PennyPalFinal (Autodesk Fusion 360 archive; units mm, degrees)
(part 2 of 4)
extrude "Extrude119" add sketch "typec" profile of L10 L11 L12 L13 A11 L18 A10 A12 L19 L16 L17 A9 against normal blind 1.07
fillet "Fillet28" radius 1
fillet "Fillet29" radius 1
extrude "Extrude120" add of existing geometry to an object
extrude "Extrude121" cut sketch "typec" profile of A1 L1 A2 L2 A3 L3 A4 L4 A11 L18 A10 A12 L19 L16 L17 A9 against normal blind 8.1 bodies "previous"
sketch "boostersketch" plane through (0, 0, -56.6398) normal (0, 0, 1) x axis (-1, 0, 0)
  line L1 (32.6862, 10.13) -> (32.6862, -10.13)
  line L2 (7.5862, 10.13) -> (32.6862, 10.13)
  line L3 (7.5862, -10.13) -> (7.5862, 10.13)
  line L4 (32.6862, -10.13) -> (7.5862, -10.13)
  line L5 (34.6862, -8.13) -> (30.6862, -8.13)
  line L6 (34.6862, -12.13) -> (34.6862, -8.13)
  line L7 (30.6862, -12.13) -> (34.6862, -12.13)
  line L8 (30.6862, -8.13) -> (30.6862, -12.13)
  line L9 (34.6862, -12.13) -> (30.6862, -8.13)
  line L10 (30.6862, -12.13) -> (34.6862, -8.13)
  line L11 (9.5862, -12.13) -> (5.5862, -12.13)
  line L12 (9.5862, -8.13) -> (9.5862, -12.13)
  line L13 (5.5862, -8.13) -> (9.5862, -8.13)
  line L14 (5.5862, -12.13) -> (5.5862, -8.13)
  line L15 (9.5862, -8.13) -> (5.5862, -12.13)
  line L16 (5.5862, -8.13) -> (9.5862, -12.13)
  line L17 (34.6862, 8.13) -> (30.6862, 8.13)
  line L18 (34.6862, 12.13) -> (34.6862, 8.13)
  line L19 (30.6862, 12.13) -> (34.6862, 12.13)
  line L20 (30.6862, 8.13) -> (30.6862, 12.13)
  line L21 (34.6862, 12.13) -> (30.6862, 8.13)
  line L22 (30.6862, 12.13) -> (34.6862, 8.13)
  line L23 (9.5862, 8.13) -> (5.5862, 8.13)
  line L24 (9.5862, 12.13) -> (9.5862, 8.13)
  line L25 (5.5862, 12.13) -> (9.5862, 12.13)
  line L26 (5.5862, 8.13) -> (5.5862, 12.13)
  line L27 (9.5862, 12.13) -> (5.5862, 8.13)
  line L28 (5.5862, 12.13) -> (9.5862, 8.13)
  point P10 (32.6862, -10.13)
  point P2 (32.6862, -10.13)
  point P15 (7.5862, -10.13)
  point P5 (7.5862, -10.13)
  point P20 (32.6862, 10.13)
  point P3 (32.6862, 10.13)
  point P25 (7.5862, 10.13)
  point P4 (7.5862, 10.13)
  point P8 (34.6862, -12.13)
  point P9 (30.6862, -12.13)
  point P7 (34.6862, -8.13)
  point P13 (9.5862, -8.13)
  point P14 (5.5862, -8.13)
  point P12 (9.5862, -12.13)
  point P18 (34.6862, 12.13)
  point P19 (30.6862, 12.13)
  point P17 (34.6862, 8.13)
  point P23 (9.5862, 12.13)
  point P24 (5.5862, 12.13)
  point P22 (9.5862, 8.13)
  horizontal L5
  perpendicular L5 L6
  parallel L5 L7
  parallel L6 L8
  coincident L9 P10
  coincident L10 P10
  coincident P2 P10
  horizontal L11
  perpendicular L11 L12
  parallel L11 L13
  parallel L12 L14
  coincident L15 P15
  coincident L16 P15
  coincident P5 P15
  horizontal L17
  perpendicular L17 L18
  parallel L17 L19
  parallel L18 L20
  coincident L21 P20
  coincident L22 P20
  coincident P3 P20
  horizontal L23
  perpendicular L23 L24
  parallel L23 L25
  parallel L24 L26
  coincident L27 P25
  coincident L28 P25
  coincident P4 P25
  dimension "d476" distance P8 P9 = 4
  dimension "d477" distance P7 P8 = 4
  dimension "d478" distance P13 P14 = 4
  dimension "d479" distance P12 P13 = 4
  dimension "d480" distance P18 P19 = 4
  dimension "d481" distance P17 P18 = 4
  dimension "d482" distance P23 P24 = 4
  dimension "d483" distance P22 P23 = 4
extrude "Extrude122" add sketch "boostersketch" profile of L1 L2 L3 L4 L5 L6 L7 L8 L11 L12 L13 L14 L17 L18 L19 L20 L23 L24 L25 L26 to an object
extrude "Extrude123" add sketch "boostersketch" profile of L1 L2 L4 L5 L6 L7 L8 L17 L18 L19 L20 to an object
extrude "Extrude124" cut sketch "boostersketch" profile of L1 L2 L3 L4 L5 L8 L12 L13 L17 L20 L23 L24 against normal blind 1.7
offset_faces "OffsetFaces4" distance -0.1
offset_faces "OffsetFaces5" distance -0.2
extrude "Extrude125" cut sketch "typec" profile of A1 L1 A2 L2 A3 L3 A4 L4 L5 A5 L6 A6 L7 A7 L8 A8 A11 L18 A10 A12 L19 L16 L17 A9 against normal blind 3
sketch "Sketch29" plane through (0, 0, -40) normal (0, 0, 1) x axis (-1, 0, 0)
  line L1 (-36.619, -31.833) -> (-36.619, 2.775)
  line L2 (34.152, -33.833) -> (-34.619, -33.833)
  line L3 (36.152, 2.775) -> (36.152, -31.833)
  line L4 (-34.619, 4.775) -> (34.152, 4.775)
  arc A1 centre (-34.619, 2.775) radius 2 clockwise from (-36.619, 2.775) to (-34.619, 4.775)
  arc A2 centre (-34.619, -31.833) radius 2 clockwise from (-34.619, -33.833) to (-36.619, -31.833)
  arc A3 centre (34.152, -31.833) radius 2 clockwise from (36.152, -31.833) to (34.152, -33.833)
  arc A4 centre (34.152, 2.775) radius 2 clockwise from (34.152, 4.775) to (36.152, 2.775)
  circle C1 centre (31.199, -29.007) radius 1.6
  circle C2 centre (31.685, -18.165) radius 0.5461
  circle C3 centre (29.145, -18.165) radius 0.5461
  circle C4 centre (31.685, -15.625) radius 0.5461
  circle C5 centre (29.145, -15.625) radius 0.5461
  circle C6 centre (15.235, -16) radius 0.4
  circle C7 centre (0, -16) radius 0.4
  circle C8 centre (-9.314, -16.78) radius 0.7
  circle C9 centre (-9.314, -14.24) radius 0.7
  circle C10 centre (-24.564, -16.805) radius 0.7
  circle C11 centre (-24.564, -14.265) radius 0.7
  circle C12 centre (-32.174, -14.148) radius 0.5
  circle C13 centre (31.685, -13.085) radius 0.5461
  circle C14 centre (29.145, -13.085) radius 0.5461
  circle C15 centre (31.685, -10.545) radius 0.5461
  circle C16 centre (29.145, -10.545) radius 0.5461
  circle C17 centre (31.685, -8.005) radius 0.5461
  circle C18 centre (29.145, -8.005) radius 0.5461
  circle C19 centre (15.235, -13.46) radius 0.4
  circle C20 centre (15.235, -10.92) radius 0.4
  circle C21 centre (0, -13.46) radius 0.4
  circle C22 centre (0, -10.92) radius 0.4
  circle C23 centre (15.235, -8.38) radius 0.4
  circle C24 centre (15.235, -5.84) radius 0.4
  circle C25 centre (0, -8.38) radius 0.4
  circle C26 centre (0, -5.84) radius 0.4
  circle C27 centre (31.335, -2.83) radius 0.5
  circle C28 centre (31.335, -0.29) radius 0.5
  circle C29 centre (31.335, 2.25) radius 0.5
  circle C30 centre (15.235, -3.3) radius 0.4
  circle C31 centre (0, -3.3) radius 0.4
  circle C32 centre (15.235, -0.76) radius 0.4
  circle C33 centre (0, -0.76) radius 0.4
  circle C34 centre (-9.314, -11.7) radius 0.7
  circle C35 centre (-9.314, -9.16) radius 0.7
  circle C36 centre (-9.314, -6.62) radius 0.7
  circle C37 centre (-24.564, -11.725) radius 0.7
  circle C38 centre (-32.174, -11.608) radius 0.5
  circle C39 centre (-24.564, -9.185) radius 0.7
  circle C40 centre (-24.564, -6.645) radius 0.7
  circle C41 centre (-9.314, -4.08) radius 0.7
  circle C42 centre (-9.314, -1.54) radius 0.7
  circle C43 centre (-9.314, 1) radius 0.7
  circle C44 centre (-24.564, -4.105) radius 0.7
  circle C45 centre (-24.564, -1.565) radius 0.7
  circle C46 centre (-24.564, 0.975) radius 0.7
  circle C47 centre (-31.285, -0.686) radius 1.6
  circle C48 centre (-31.285, -0.686) radius 3
  circle C49 centre (31.199, -29.007) radius 3
  concentric C47 C48
  concentric C1 C49
  dimension "d494" diameter C48 = 6
  dimension "d495" diameter C49 = 6
extrude "Extrude126" add sketch "Sketch29" profile of C47 C48 to an object bodies "chamber"
extrude "Extrude127" add sketch "Sketch29" profile of C1 C49 to an object
sketch "coinplateboss" plane through (0, 0, 34.7705) normal (0, 0, 1) x axis (-1, 0, 0)
  line L1 (17.5, 9) -> (-17.5, 9)
  line L2 (17.5, 55) -> (17.5, 9)
  line L3 (-17.5, 55) -> (17.5, 55)
  line L4 (-17.5, 9) -> (-17.5, 55)
  line L5 (17.486, 0) -> (-20, 0)
  line L6 (0, 22) -> (0, 42)
  circle C1 centre (13.1388, 44.2682) radius 0.9
  circle C2 centre (13.1388, 44.2682) radius 3
  circle C3 centre (-13.1388, 44.2682) radius 0.9
  circle C4 centre (-13.1388, 44.2682) radius 3
  circle C5 centre (13.1388, -44.2682) radius 0.9
  circle C6 centre (13.1388, -44.2682) radius 3
  circle C7 centre (-13.1388, -44.2682) radius 0.9
  circle C8 centre (-13.1388, -44.2682) radius 3
  horizontal L5
  concentric C1 C2
  vertical L6
  symmetric C1 L6 C3
  symmetric C2 L6 C4
  symmetric L5 C1 C5
  symmetric L5 C2 C6
  symmetric L5 C3 C7
  symmetric L5 C4 C8
  dimension "d501" diameter C1 = 1.8
  dimension "d502" diameter C2 = 6
extrude "Extrude128" cut sketch "coinplateboss" profile of C1 C3 C5 C7 against normal blind 10
extrude "Extrude129" add sketch "coinplateboss" profile of C1 C2 C3 C4 to an object
extrude "Extrude130" add sketch "coinplateboss" profile of C5 C6 C7 C8 to an object
sketch "Sketch32" plane through (0, 0, 0) normal (0, 1, 0) x axis (1, 0, 0)
  line L1 (19.9, -26) -> (-17.5, -26)
  line L2 (-17.5, 32.7705) -> (17.5, 32.7705)
  line L3 (24.316, -26) -> (24.316, -32.0538)
  line L4 (19.9, -26) -> (24.316, -26)
  line L5 (-21.76, -26) -> (-21.76, -32.4924)
  line L6 (-17.5, -26) -> (-21.76, -26)
  line L7 (-21.76, -26) -> (-21.76, -32.4924)
  line L8 (-17.5, -26) -> (-21.76, -26)
  line L9 (19.9, -26) -> (-17.5, -26)
  line L10 (19.9, -26) -> (24.316, -26)
  line L11 (24.316, -26) -> (24.316, -32.0538)
  line L12 (-17.5, -32.8326) -> (17.5, -32.8326)
  line L13 (50.2705, 0) -> (0, 0)
  line L14 (-50.2705, 0) -> (0, 0)
  line L15 (50.2362, 1.5) -> (49.2705, 1.5)
  line L16 (51.7705, -1.5) -> (51.7705, 1.5)
  line L17 (49.2705, -1.5) -> (50.2362, -1.5)
  line L18 (48.7705, 1) -> (48.7705, -1)
  line L19 (51.7705, -1.5) -> (48.7705, 1.5)
  line L20 (48.7705, -1.5) -> (51.7705, 1.5)
  line L21 (0, -13) -> (0, 0)
  line L22 (-50.2362, 1.5) -> (-49.2705, 1.5)
  line L23 (-49.2705, -1.5) -> (-50.2362, -1.5)
  line L24 (-48.7705, 1) -> (-48.7705, -1)
  line L25 (-17.5, 32.7705) -> (17.5, 32.7705)
  line L26 (-17.5, 30.7705) -> (17.5, 30.7705)
  line L27 (46.7705, 1) -> (46.7705, -1)
  line L28 (-46.7705, 1) -> (-46.7705, -1)
  line L29 (49.2705, -1.8) -> (50.221, -1.8)
  line L30 (48.4705, 1) -> (48.4705, -1)
  line L31 (50.221, 1.8) -> (49.2705, 1.8)
  line L32 (-49.2705, -1.8) -> (-50.221, -1.8)
  line L33 (-48.4705, 1) -> (-48.4705, -1)
  line L34 (-50.221, 1.8) -> (-49.2705, 1.8)
  arc A1 centre (-17.5, 0) radius 32.7705 clockwise from (-17.5, -32.7705) to (-36, -27.0491)
  arc A2 centre (17.5, 0) radius 32.7705 clockwise from (36, -27.0491) to (17.5, -32.7705)
  arc A3 centre (-17.5, 0) radius 32.7705 clockwise from (-36, -27.0491) to (-17.5, 32.7705)
  arc A4 centre (17.5, 0) radius 32.7705 clockwise from (17.5, 32.7705) to (36, -27.0491)
  arc A5 centre (49.2705, -1) radius 0.5 clockwise from (49.2705, -1.5) to (48.7705, -1)
  arc A6 centre (49.2705, 1) radius 0.5 clockwise from (48.7705, 1) to (49.2705, 1.5)
  arc A7 centre (-49.2705, -1) radius 0.5 clockwise from (-48.7705, -1) to (-49.2705, -1.5)
  arc A8 centre (-49.2705, 1) radius 0.5 clockwise from (-49.2705, 1.5) to (-48.7705, 1)
  arc A9 centre (17.5, 0) radius 30.7705 clockwise from (34.8709, -25.3983) to (24.316, -30.0061)
  arc A10 centre (-17.5, 0) radius 30.7705 clockwise from (-21.76, -30.4742) to (-34.8709, -25.3983)
  arc A11 centre (49.2705, -1) radius 2.5 clockwise from (48.1026, -3.2104) to (46.7705, -1)
  arc A12 centre (49.2705, 1) radius 2.5 clockwise from (46.7705, 1) to (48.1026, 3.2104)
  arc A13 centre (17.5, 0) radius 30.7705 clockwise from (48.1026, -3.2104) to (34.8709, -25.3983)
  arc A14 centre (17.5, 0) radius 30.7705 clockwise from (17.5, 30.7705) to (48.1026, 3.2104)
  arc A15 centre (-49.2705, -1) radius 2.5 clockwise from (-46.7705, -1) to (-48.1026, -3.2104)
  arc A16 centre (-49.2705, 1) radius 2.5 clockwise from (-48.1026, 3.2104) to (-46.7705, 1)
  arc A17 centre (-17.5, 0) radius 30.7705 clockwise from (-48.1026, 3.2104) to (-17.5, 30.7705)
  arc A18 centre (-17.5, 0) radius 30.7705 clockwise from (-34.8709, -25.3983) to (-48.1026, -3.2104)
  arc A19 centre (49.2705, -1) radius 0.8 clockwise from (49.2705, -1.8) to (48.4705, -1)
  arc A20 centre (49.2705, 1) radius 0.8 clockwise from (48.4705, 1) to (49.2705, 1.8)
  arc A21 centre (-49.2705, -1) radius 0.8 clockwise from (-48.4705, -1) to (-49.2705, -1.8)
  arc A22 centre (-49.2705, 1) radius 0.8 clockwise from (-49.2705, 1.8) to (-48.4705, 1)
  point P3 (19.9, -26)
  point P18 (19.9, -26)
  point P2 (-17.5, -26)
  point P21 (-17.5, -26)
  point P1 (0, 0)
  point P30 (0, 0)
  point P31 (50.2705, 0)
  point P32 (-50.2705, 0)
  point P37 (50.2705, 0)
  point P38 (-50.2705, 0)
  point P39 (50.2362, -1.5)
  point P40 (50.2362, 1.5)
  point P36 (48.7705, -1.5)
  point P33 (48.7705, 1.5)
  point P55 (-50.2362, -1.5)
  point P54 (-50.2362, 1.5)
  point P41 (49.2705, -1.5)
  point P50 (-49.2705, -1.5)
  point P42 (48.7705, -1)
  point P49 (-48.7705, -1)
  point P44 (49.2705, 1.5)
  point P52 (-49.2705, 1.5)
  point P45 (48.7705, 1)
  point P53 (-48.7705, 1)
  point P70 (24.316, -30.0061)
  point P71 (-21.76, -30.4742)
  point P73 (46.7705, -1)
  point P80 (-46.7705, -1)
  point P74 (46.7705, 1)
  point P82 (-46.7705, 1)
  point P76 (48.1026, -3.2104)
  point P81 (-48.1026, -3.2104)
  point P78 (48.1026, 3.2104)
  point P84 (-48.1026, 3.2104)
  point P92 (50.221, -1.8)
  point P93 (50.221, 1.8)
  point P86 (49.2705, -1.8)
  point P95 (-49.2705, -1.8)
  point P88 (48.4705, -1)
  point P97 (-48.4705, -1)
  point P89 (48.4705, 1)
  point P98 (-48.4705, 1)
  point P91 (49.2705, 1.8)
  point P100 (-49.2705, 1.8)
  point P94 (-50.221, -1.8)
  point P101 (-50.221, 1.8)
  point P35 (51.7705, -1.5)
  point P34 (51.7705, 1.5)
  perpendicular L1 L3
  coincident P3 P18
  perpendicular L1 L5
  coincident P2 P21
  coincident P1 P30
  coincident A4 P31
  horizontal L13
  coincident A3 P32
  parallel L13 L14
  horizontal L15
  perpendicular L15 L16
  parallel L15 L17
  parallel L16 L18
  coincident L19 P37
  coincident L20 P37
  coincident P31 P37
  coincident P32 P38
  coincident A4 P39
  coincident A4 P40
  coincident P36 L17
  coincident P36 L18
  tangent L17 A5
  tangent L18 A5
  coincident P33 L15
  coincident P33 L18
  tangent L15 A6
  tangent L18 A6
  equal A5 A6
  perpendicular L14 L21
  symmetric P39 L21 P55
  symmetric P40 L21 P54
  symmetric P41 L21 P50
  symmetric P42 L21 P49
  symmetric A5 L21 A7
  symmetric P44 L21 P52
  symmetric P45 L21 P53
  symmetric A6 L21 A8
  concentric A2 A9
  coincident L3 P70
  concentric A1 A10
  coincident L5 P71
  concentric A5 A11
  concentric A6 A12
  tangent L27 A12
  tangent A11 L27
  concentric A4 A13
  concentric A13 A14
  symmetric L21 P73 P80
  symmetric L21 A11 A15
  symmetric L21 P74 P82
  symmetric L21 A12 A16
  symmetric L21 P76 P81
  symmetric L21 P78 P84
  concentric A3 A17
  concentric A17 A18
  concentric A5 A19
  concentric A6 A20
  tangent A19 L30
  tangent L30 A20
  tangent A20 L31
  tangent L29 A19
  coincident A4 P92
  coincident A4 P93
  symmetric L21 P86 P95
  symmetric L21 P88 P97
  symmetric L21 A19 A21
  symmetric L21 P89 P98
  symmetric L21 P91 P100
  symmetric L21 A20 A22
  symmetric L21 P92 P94
  symmetric L21 P93 P101
  dimension "d514" distance L3 = 0
  dimension "d515" distance P35 P36 = 3
  dimension "d516" distance P34 P35 = 3
  dimension "d521" radius A5 = 0.5
  dimension "d533" distance L2 = 0
  dimension "d534" = -2
extrude "Extrude133" add sketch "Sketch32" profile of A3 A4 L15 L17 L18 A5 A6 A7 A8 L22 L23 L24 along normal blind 55 and against normal blind 55
extrude "Extrude134" new body sketch "Sketch32" profile of A1 A2 L2 A3 A4 L3 L5 L11 L7 A14 A9 A10 A18 L25 L26 L27 A11 A12 A15 L28 A16 L30 L31 A19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 along normal blind 55 and against normal blind 55 bodies "drawer"
offset_faces "OffsetFaces6" distance -0.2
sketch "Sketch33" plane through (0, 55, 0) normal (0, 1, 0) x axis (-1, 0, 0)
  line L1 (21.76, 30.4742) -> (21.76, 32.2907)
  line L2 (-17.5, -30.7705) -> (17.5, -30.7705)
  line L3 (-24.316, 31.8493) -> (-24.316, 30.0061)
  line L4 (17.5, -32.5705) -> (-17.5, -32.5705)
  line L5 (-24.316, 30) -> (-24.316, 31.8493)
  line L6 (21.76, 30) -> (21.76, 32.2907)
  line L7 (-20.316, 26) -> (0, 26)
  line L8 (17.76, 26) -> (0, 26)
  line L9 (17.5, -34.7705) -> (-17.5, -34.7705)
  line L10 (17.5, -29.2705) -> (-17.5, -29.2705)
  line L11 (17.5, -32.5705) -> (-17.5, -32.5705)
  line L12 (17.5, -30.5705) -> (-17.5, -30.5705)
  line L13 (48.4705, 1) -> (48.4705, -1)
  line L14 (50.0207, 1.8) -> (49.2705, 1.8)
  line L15 (49.2705, -1.8) -> (50.0207, -1.8)
  line L16 (46.7705, -1) -> (46.7705, 1)
  line L17 (-49.2705, 1.8) -> (-50.0207, 1.8)
  line L18 (-48.4705, -1) -> (-48.4705, 1)
  line L19 (-50.0207, -1.8) -> (-49.2705, -1.8)
  line L20 (-46.7705, 1) -> (-46.7705, -1)
  line L21 (-46.7705, 1) -> (-46.7705, -1)
  line L22 (46.7705, -1) -> (46.7705, 1)
  line L23 (-43.7705, 1) -> (-43.7705, -1)
  line L24 (43.7705, -1) -> (43.7705, 1)
  line L25 (-17.5, 34.7705) -> (17.5, 34.7705)
  line L26 (-17.5, 32.5705) -> (17.5, 32.5705)
  line L27 (-2, 32.5705) -> (-2, 26)
  line L28 (-20.316, 28) -> (0, 28)
  line L29 (17.76, 28) -> (0, 28)
  line L30 (-20.316, 31) -> (0, 31)
  line L31 (17.76, 31) -> (0, 31)
  line L32 (-20.316, 31) -> (-20.316, 28)
  line L33 (17.76, 31) -> (17.76, 28)
  line L34 (-20, 26) -> (-20.316, 28)
  line L35 (17.76, 26) -> (17.76, 28)
  arc A1 centre (17.5, 0) radius 32.5705 clockwise from (21.76, 32.2907) to (50.0207, 1.8)
  arc A2 centre (-17.5, 0) radius 32.5705 clockwise from (-50.0207, 1.8) to (-24.316, 31.8493)
  arc A3 centre (-17.5, 0) radius 32.5705 clockwise from (-17.5, -32.5705) to (-50.0207, -1.8)
  arc A4 centre (17.5, 0) radius 32.5705 clockwise from (50.0207, -1.8) to (17.5, -32.5705)
  arc A5 centre (17.5, 0) radius 29.5705 clockwise from (47.0705, 0) to (47.0705, -0.0001)
  arc A6 centre (17.5, 0) radius 34.7705 clockwise from (36, 29.4404) to (17.5, -34.7705)
  arc A7 centre (-17.5, 0) radius 34.7705 clockwise from (-17.5, -34.7705) to (-36, 29.4404)
  arc A8 centre (-17.5, 0) radius 34.7705 clockwise from (-36, 29.4404) to (-17.5, 34.7705)
  arc A9 centre (17.5, 0) radius 34.7705 clockwise from (17.5, 34.7705) to (36, 29.4404)
  arc A10 centre (-17.5, 0) radius 29.2705 clockwise from (-33.0737, 24.7835) to (-24.316, 28.4659)
  arc A11 centre (17.5, 0) radius 29.2705 clockwise from (21.76, 28.9589) to (33.0737, 24.7835)
  arc A12 centre (17.5, 0) radius 32.5705 clockwise from (21.76, 32.2907) to (34.8295, 27.5777)
  arc A13 centre (-17.5, 0) radius 32.5705 clockwise from (-34.8295, 27.5777) to (-24.316, 31.8493)
  arc A14 centre (17.5, 0) radius 30.5705 clockwise from (21.76, 30.2722) to (33.7653, 25.8843)
  arc A15 centre (-17.5, 0) radius 30.5705 clockwise from (-33.7653, 25.8843) to (-24.316, 29.801)
  arc A16 centre (49.2705, 1) radius 0.8 clockwise from (48.4705, 1) to (49.2705, 1.8)
  arc A17 centre (49.2705, -1) radius 0.8 clockwise from (49.2705, -1.8) to (48.4705, -1)
  arc A18 centre (49.2705, -1) radius 2.5 clockwise from (48.1026, -3.2104) to (46.7705, -1)
  arc A19 centre (49.2705, 1) radius 2.5 clockwise from (46.7705, 1) to (48.1026, 3.2104)
  arc A20 centre (-49.2705, 1) radius 0.8 clockwise from (-49.2705, 1.8) to (-48.4705, 1)
  arc A21 centre (-49.2705, -1) radius 0.8 clockwise from (-48.4705, -1) to (-49.2705, -1.8)
  arc A22 centre (-49.2705, 1) radius 2.5 clockwise from (-48.1026, 3.2104) to (-46.7705, 1)
  arc A23 centre (-49.2705, -1) radius 2.5 clockwise from (-46.7705, -1) to (-48.1026, -3.2104)
  arc A24 centre (-49.2705, -1) radius 2.5 clockwise from (-46.7705, -1) to (-49.8902, -3.422)
  arc A25 centre (-49.2705, 1) radius 2.5 clockwise from (-49.8902, 3.422) to (-46.7705, 1)
  arc A26 centre (-17.5, 0) radius 32.5705 clockwise from (-49.8902, 3.422) to (-34.8295, 27.5777)
  arc A27 centre (-17.5, 0) radius 32.5705 clockwise from (-17.5, -32.5705) to (-49.8902, -3.422)
  arc A28 centre (-17.5, 0) radius 29.2705 clockwise from (-46.2327, 5.585) to (-33.0737, 24.7835)
  arc A29 centre (-17.5, 0) radius 29.2705 clockwise from (-17.5, -29.2705) to (-46.2327, -5.585)
  arc A30 centre (-17.5, 0) radius 30.5705 clockwise from (-47.913, 3.0993) to (-33.7653, 25.8843)
  arc A31 centre (-17.5, 0) radius 30.5705 clockwise from (-17.5, -30.5705) to (-47.913, -3.0993)
  arc A32 centre (49.2705, 1) radius 2.5 clockwise from (46.7705, 1) to (49.8902, 3.422)
  arc A33 centre (49.2705, -1) radius 2.5 clockwise from (49.8902, -3.422) to (46.7705, -1)
  arc A34 centre (17.5, 0) radius 32.5705 clockwise from (34.8295, 27.5777) to (49.8902, 3.422)
  arc A35 centre (17.5, 0) radius 32.5705 clockwise from (49.8902, -3.422) to (17.5, -32.5705)
  arc A36 centre (17.5, 0) radius 29.2705 clockwise from (46.2327, -5.585) to (17.5, -29.2705)
  arc A37 centre (17.5, 0) radius 29.2705 clockwise from (33.0737, 24.7835) to (46.2327, 5.585)
  arc A38 centre (49.2705, 1) radius 4.5 clockwise from (49.6049, 5.4876) to (49.6643, 5.4827)
  arc A39 centre (17.5, 0) radius 30.5705 clockwise from (47.913, -3.0993) to (17.5, -30.5705)
  arc A40 centre (17.5, 0) radius 30.5705 clockwise from (33.7653, 25.8843) to (47.913, 3.0993)
  arc A41 centre (-49.2705, 1) radius 5.5 clockwise from (-46.2327, 5.585) to (-43.7705, 1)
  arc A42 centre (-49.2705, -1) radius 5.5 clockwise from (-43.7705, -1) to (-46.2327, -5.585)
  arc A43 centre (49.2705, 1) radius 5.5 clockwise from (43.7705, 1) to (46.2327, 5.585)
  arc A44 centre (49.2705, -1) radius 5.5 clockwise from (46.2327, -5.585) to (43.7705, -1)
  arc A45 centre (17.5, 0) radius 32.5705 clockwise from (17.5, 32.5705) to (34.8295, 27.5777)
  arc A46 centre (-17.5, 0) radius 32.5705 clockwise from (-34.8295, 27.5777) to (-17.5, 32.5705)
  arc A47 centre (17.5, 0) radius 30.5705 clockwise from (21.76, 30.2722) to (33.7653, 25.8843)
  arc A48 centre (-17.5, 0) radius 30.5705 clockwise from (-33.7653, 25.8843) to (-24.3111, 29.8021)
  arc A49 centre (17.5, 0) radius 29.2705 clockwise from (21.6272, 28.9781) to (33.0737, 24.7835)
  arc A50 centre (-17.5, 0) radius 29.2705 clockwise from (-33.0737, 24.7835) to (-24.0366, 28.5313)
  arc A51 centre (-20.316, 30) radius 4 clockwise from (-20.316, 26) to (-24.316, 30)
  arc A52 centre (17.76, 30) radius 4 clockwise from (21.76, 30) to (17.76, 26)
  point P10 (-24.316, 31.8493)
  point P19 (-24.316, 31.8493)
  point P3 (21.76, 32.2907)
  point P20 (21.76, 32.2907)
  point P44 (-24.316, 28.4659)
  point P45 (21.76, 28.9589)
  point P68 (-24.316, 29.801)
  point P69 (21.76, 30.2722)
  point P101 (-49.8902, -3.422)
  point P108 (-47.913, 3.0993)
  point P109 (-47.913, -3.0993)
  point P119 (49.6049, 5.4876)
  point P120 (47.913, -3.0993)
  point P121 (47.913, 3.0993)
  point P159 (-24.3111, 29.8021)
  point P160 (-24.0366, 28.5313)
  point P161 (21.6272, 28.9781)
  point P162 (-2, 26)
  point P163 (-2, 32.5705)
  point P172 (-20, 26)
  coincident P10 P19
  parallel L3 L5
  coincident P3 P20
  parallel L1 L6
  perpendicular L5 L7
  parallel L7 L8
  tangent L10 A36
  concentric A8 A10
  coincident L5 P44
  concentric A9 A11
  coincident L6 P45
  concentric A9 A12
  concentric A8 A13
  concentric A13 A15
  coincident L5 P68
  concentric A12 A14
  coincident L6 P69
  coincident A3 P101
  concentric A7 A26
  concentric A6 A35
  tangent L11 A27
  tangent L11 A35
  concentric A26 A30
  concentric A26 A27
  tangent A24 L21
  tangent L21 A25
  concentric A7 A28
  concentric A28 A29
  coincident A22 P108
  coincident A23 P109
  concentric A30 A31
  concentric A35 A39
  concentric A32 A38
  tangent L22 A33
  tangent A32 L22
  concentric A6 A36
  concentric A36 A37
  coincident A1 P119
  coincident A18 P120
  coincident A19 P121
  concentric A39 A40
  tangent L5 A51
  tangent L7 A51
  tangent L8 A52
  tangent L6 A52
  equal A51 A52
  concentric A45 A47
  concentric A46 A48
  concentric A47 A49
  concentric A48 A50
  coincident A51 P159
  coincident A51 P160
  coincident A52 P161
  coincident L7 P162
  coincident L26 P163
  perpendicular L26 L27
  perpendicular L30 L32
  perpendicular L31 L33
  coincident L7 P172
  perpendicular L8 L35
  dimension "d571" = -2
  dimension "d597" = -2.2
  dimension "d598" distance A15 A46 = 2
  dimension "d601" radius A51 = 4
  dimension "d691" = 2
  dimension "d692" = -2
  dimension "d693" = 3
  dimension "d694" = -3
extrude "Extrude136" new body sketch "Sketch33" profile of A1 L1 L2 L3 A2 A3 L4 A4 L5 L6 A37 A29 L10 A10 A11 A35 L11 A27 A12 A13 along normal blind 2
extrude "Extrude137" new body of existing geometry blind 2 bodies "drawerfront"
move "Move10"
extrude "Extrude138" new body sketch "Sketch33" profile of L5 L6 L7 L8 A37 A29 L10 A10 A11 along normal blind 1.8 bodies "acrylic"
move "Move11"
offset_faces "OffsetFaces7" distance 1
extrude "Extrude139" add sketch "Sketch33" profile of L1 L3 L5 L6 L7 L8 A37 A29 L10 A10 A11 A41 L23 A42 A43 L24 A44 A46 L26 A45 A50 A49 A51 A52 along normal blind 2 bodies "acrylic"
extrude "Extrude140" add sketch "Sketch33" profile of L3 A2 L5 L7 L8 A37 A29 L10 A10 A11 A27 A13 A31 A15 A22 A25 A41 L23 A42 A43 L24 A44 A46 A48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 along normal blind 2
move "Move12"
extrude "Extrude142" add sketch "Sketch33" profile of A3 L4 A4 A35 L11 A27 A40 L12 A31 A18 A23 A24 A33 against normal blind 2
remove_body "RemoveBody29"
copy_paste_bodies "CopyPasteBodies2"
move "Move14"
extrude "Extrude143" add sketch "Sketch33" profile of A1 L1 L3 A2 A3 L4 A4 L5 L6 A35 L11 A27 A12 A13 A14 A40 L12 A31 A15 A18 A19 A22 A23 A25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 against normal blind 3.8
extrude "Extrude144" add of existing geometry blind 2
extrude "Extrude145" add sketch "Sketch33" profile of L1 L3 L5 L6 L7 L8 A46 L26 A45 A51 A52 to an object
sketch "accrylicsketch" plane through (0, 55, 0) normal (0, 1, 0) x axis (-1, 0, 0)
  line L1 (-46.7705, -1) -> (-46.7705, 1)
  line L2 (17.5, -32.5705) -> (-17.5, -32.5705)
  line L3 (46.7705, 1) -> (46.7705, -1)
  line L4 (-17.5, 32.5705) -> (17.5, 32.5705)
  line L5 (17.76, 26) -> (-20.316, 26)
  line L6 (43.7705, -1) -> (43.7705, 1)
  line L7 (-17.5, -29.2705) -> (17.5, -29.2705)
  line L8 (-43.7705, 1) -> (-43.7705, -1)
  line L9 (-44.7705, 1) -> (-44.7705, -1)
  line L10 (-17.5, -30.2705) -> (17.5, -30.2705)
  line L11 (44.7705, -1) -> (44.7705, 1)
  line L12 (-24.0366, 29.5563) -> (-24.0366, 28.5313)
  line L13 (21.6272, 29.9878) -> (21.6272, 28.9781)
  arc A1 centre (-17.5, 0) radius 32.5705 clockwise from (-49.8902, 3.422) to (-17.5, 32.5705)
  arc A2 centre (-49.2705, 1) radius 2.5 clockwise from (-49.8902, 3.422) to (-46.7705, 1)
  arc A3 centre (-49.2705, -1) radius 2.5 clockwise from (-46.7705, -1) to (-49.8902, -3.422)
  arc A4 centre (-17.5, 0) radius 32.5705 clockwise from (-17.5, -32.5705) to (-49.8902, -3.422)
  arc A5 centre (17.5, 0) radius 32.5705 clockwise from (49.8902, -3.422) to (17.5, -32.5705)
  arc A6 centre (49.2705, -1) radius 2.5 clockwise from (49.8902, -3.422) to (46.7705, -1)
  arc A7 centre (49.2705, 1) radius 2.5 clockwise from (46.7705, 1) to (49.8902, 3.422)
  arc A8 centre (17.5, 0) radius 32.5705 clockwise from (17.5, 32.5705) to (49.8902, 3.422)
  arc A9 centre (-20.316, 30) radius 4 clockwise from (-20.316, 26) to (-24.0366, 28.5313)
  arc A10 centre (17.76, 30) radius 4 clockwise from (21.6272, 28.9781) to (17.76, 26)
  arc A11 centre (17.5, 0) radius 29.2705 clockwise from (21.6272, 28.9781) to (46.2327, 5.585)
  arc A12 centre (49.2705, 1) radius 5.5 clockwise from (43.7705, 1) to (46.2327, 5.585)
  arc A13 centre (49.2705, -1) radius 5.5 clockwise from (46.2327, -5.585) to (43.7705, -1)
  arc A14 centre (17.5, 0) radius 29.2705 clockwise from (46.2327, -5.585) to (17.5, -29.2705)
  arc A15 centre (-17.5, 0) radius 29.2705 clockwise from (-17.5, -29.2705) to (-46.2327, -5.585)
  arc A16 centre (-49.2705, -1) radius 5.5 clockwise from (-43.7705, -1) to (-46.2327, -5.585)
  arc A17 centre (-49.2705, 1) radius 5.5 clockwise from (-46.2327, 5.585) to (-43.7705, 1)
  arc A18 centre (-17.5, 0) radius 29.2705 clockwise from (-46.2327, 5.585) to (-24.0366, 28.5313)
  arc A19 centre (17.5, 0) radius 30.2705 clockwise from (21.6272, 29.9878) to (47.3435, 5.0665)
  arc A20 centre (-17.5, 0) radius 30.2705 clockwise from (-47.3435, 5.0665) to (-24.0366, 29.5563)
  arc A21 centre (-49.2705, 1) radius 4.5 clockwise from (-47.3435, 5.0665) to (-44.7705, 1)
  arc A22 centre (-49.2705, -1) radius 4.5 clockwise from (-44.7705, -1) to (-47.3435, -5.0665)
  arc A23 centre (-17.5, 0) radius 30.2705 clockwise from (-17.5, -30.2705) to (-47.3435, -5.0665)
  arc A24 centre (17.5, 0) radius 30.2705 clockwise from (47.3435, -5.0665) to (17.5, -30.2705)
  arc A25 centre (49.2705, -1) radius 4.5 clockwise from (47.3435, -5.0665) to (44.7705, -1)
  arc A26 centre (49.2705, 1) radius 4.5 clockwise from (44.7705, 1) to (47.3435, 5.0665)
  point P20 (-24.0366, 28.5313)
  point P54 (-24.0366, 28.5313)
  point P24 (21.6272, 28.9781)
  point P56 (21.6272, 28.9781)
  coincident P20 P54
  vertical L12
  coincident P24 P56
  parallel L12 L13
  concentric A11 A19
  concentric A18 A20
  concentric A17 A21
  concentric A16 A22
  concentric A15 A23
  concentric A14 A24
  concentric A13 A25
  concentric A12 A26
  tangent L11 A26
  tangent A21 L9
  tangent A23 L10
  tangent L9 A22
  tangent L10 A24
  tangent A25 L11
extrude "Extrude146" new body sketch "accrylicsketch" profile of A9 L5 A10 A11 A12 L6 A13 A14 L7 A15 A16 L8 A17 A18 A26 L11 A25 A24 A19 L10 A22 L9 A20 A23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 against normal blind 3.8 bodies "acrylic"
extrude "Extrude147" cut of existing geometry blind -2
sketch "drawerpanel" plane through (0, -55, 0) normal (0, -1, 0) x axis (1, 0, 0)
  line L1 (36, 29.4404) -> (36, 27.0491)
  line L2 (-17.5, 34.7705) -> (17.5, 34.7705)
  line L3 (-36, 27.0491) -> (-36, 29.4404)
  line L4 (17.5, 32.7705) -> (-17.5, 32.7705)
  line L5 (43.7705, -1) -> (43.7705, 1)
  line L6 (-17.5, -29.2705) -> (17.5, -29.2705)
  line L7 (-43.7705, 1) -> (-43.7705, -1)
  line L8 (20.316, 26) -> (-17.76, 26)
  line L9 (-17.5, 32.5705) -> (17.5, 32.5705)
  line L10 (-46.7705, -1) -> (-46.7705, 1)
  line L11 (17.5, -32.5705) -> (-17.5, -32.5705)
  line L12 (46.7705, 1) -> (46.7705, -1)
  line L13 (24.0366, 28.5313) -> (24.0366, 29.5563)
  line L14 (-17.76, 26) -> (20.316, 26)
  line L15 (-21.6272, 29.9878) -> (-21.6272, 28.9781)
  line L16 (-44.7705, -1) -> (-44.7705, 1)
  line L17 (17.5, -30.2705) -> (-17.5, -30.2705)
  line L18 (44.7705, 1) -> (44.7705, -1)
  line L19 (-21.6272, 32.308) -> (-21.6272, 29.9878)
  line L20 (24.0366, 31.9079) -> (24.0366, 29.5563)
  line L21 (-21.6272, 32.5096) -> (-21.6272, 32.308)
  line L22 (24.0366, 32.2) -> (24.0366, 31.9079)
  arc A1 centre (17.5, 0) radius 34.7705 clockwise from (17.5, 34.7705) to (36, 29.4404)
  arc A2 centre (-17.5, 0) radius 34.7705 clockwise from (-36, 29.4404) to (-17.5, 34.7705)
  arc A3 centre (-17.5, 0) radius 32.7705 clockwise from (-36, 27.0491) to (-17.5, 32.7705)
  arc A4 centre (17.5, 0) radius 32.7705 clockwise from (17.5, 32.7705) to (36, 27.0491)
  arc A5 centre (17.5, 0) radius 29.2705 clockwise from (24.0366, 28.5313) to (46.2327, 5.585)
  arc A6 centre (49.2705, 1) radius 5.5 clockwise from (43.7705, 1) to (46.2327, 5.585)
  arc A7 centre (49.2705, -1) radius 5.5 clockwise from (46.2327, -5.585) to (43.7705, -1)
  arc A8 centre (17.5, 0) radius 29.2705 clockwise from (46.2327, -5.585) to (17.5, -29.2705)
  arc A9 centre (-17.5, 0) radius 29.2705 clockwise from (-17.5, -29.2705) to (-46.2327, -5.585)
  arc A10 centre (-49.2705, -1) radius 5.5 clockwise from (-43.7705, -1) to (-46.2327, -5.585)
  arc A11 centre (-49.2705, 1) radius 5.5 clockwise from (-46.2327, 5.585) to (-43.7705, 1)
  arc A12 centre (-17.5, 0) radius 29.2705 clockwise from (-46.2327, 5.585) to (-21.6272, 28.9781)
  arc A13 centre (-17.76, 30) radius 4 clockwise from (-17.76, 26) to (-21.6272, 28.9781)
  arc A14 centre (20.316, 30) radius 4 clockwise from (24.0366, 28.5313) to (20.316, 26)
  arc A15 centre (17.5, 0) radius 32.5705 clockwise from (17.5, 32.5705) to (49.8902, 3.422)
  arc A16 centre (-17.5, 0) radius 32.5705 clockwise from (-49.8902, 3.422) to (-17.5, 32.5705)
  arc A17 centre (-49.2705, 1) radius 2.5 clockwise from (-49.8902, 3.422) to (-46.7705, 1)
  arc A18 centre (-49.2705, -1) radius 2.5 clockwise from (-46.7705, -1) to (-49.8902, -3.422)
  arc A19 centre (-17.5, 0) radius 32.5705 clockwise from (-17.5, -32.5705) to (-49.8902, -3.422)
  arc A20 centre (17.5, 0) radius 32.5705 clockwise from (49.8902, -3.422) to (17.5, -32.5705)
  arc A21 centre (49.2705, -1) radius 2.5 clockwise from (49.8902, -3.422) to (46.7705, -1)
  arc A22 centre (49.2705, 1) radius 2.5 clockwise from (46.7705, 1) to (49.8902, 3.422)
  arc A23 centre (20.316, 30) radius 4 clockwise from (24.0366, 28.5313) to (20.316, 26)
  arc A24 centre (-17.76, 30) radius 4 clockwise from (-17.76, 26) to (-21.6272, 28.9781)
  arc A25 centre (-17.5, 0) radius 30.2705 clockwise from (-47.3435, 5.0665) to (-21.6272, 29.9878)
  arc A26 centre (-49.2705, 1) radius 4.5 clockwise from (-47.3435, 5.0665) to (-44.7705, 1)
  arc A27 centre (-49.2705, -1) radius 4.5 clockwise from (-44.7705, -1) to (-47.3435, -5.0665)
  arc A28 centre (-17.5, 0) radius 30.2705 clockwise from (-17.5, -30.2705) to (-47.3435, -5.0665)
  arc A29 centre (17.5, 0) radius 30.2705 clockwise from (47.3435, -5.0665) to (17.5, -30.2705)
  arc A30 centre (49.2705, -1) radius 4.5 clockwise from (47.3435, -5.0665) to (44.7705, -1)
  arc A31 centre (49.2705, 1) radius 4.5 clockwise from (44.7705, 1) to (47.3435, 5.0665)
  arc A32 centre (17.5, 0) radius 30.2705 clockwise from (24.0366, 29.5563) to (47.3435, 5.0665)
  point P53 (-21.6272, 29.9878)
  point P70 (-21.6272, 29.9878)
  point P71 (-21.6272, 32.308)
  point P46 (24.0366, 29.5563)
  point P72 (24.0366, 29.5563)
  point P73 (24.0366, 31.9079)
  point P74 (-21.6272, 32.5096)
  coincident P53 P70
  coincident A16 P71
  parallel L15 L19
  coincident P46 P72
  coincident A15 P73
  parallel L13 L20
  coincident A3 P74
  parallel L19 L21
  parallel L20 L22
extrude "Extrude148" add sketch "drawerpanel" profile of A3 L4 A4 A13 L8 A14 A15 L9 A16 L13 A23 L14 A24 L15 L19 L20 L21 L22 against normal blind 2
extrude "Extrude149" new body sketch "drawerpanel" profile of A5 A6 L5 A7 A8 L6 A9 A10 L7 A11 A12 A15 A16 A17 L10 A18 A19 L11 A20 A21 L12 A22 L13 L15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 against normal blind 2
copy_paste_bodies "CopyPasteBodies3"
move "Move15"
extrude "Extrude150" add sketch "drawerpanel" profile of A15 A16 A17 L10 A18 A19 L11 A20 A21 L12 A22 A25 A26 L16 A27 A28 L17 A29 A30 L18 A31 A32 L19 L20 against normal blind 3.8
extrude "Extrude151" new body sketch "drawerpanel" profile of A5 A6 L5 A7 A8 L6 A9 A10 L7 A11 A12 A13 L8 A14 L13 A23 L14 A24 L15 A25 A26 L16 A27 A28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 against normal blind 3.8 bodies "acrbck"
extrude "Extrude152" cut of existing geometry blind -2
external_derived "Sketch3"
derived_instance "DerivedInstance6"
derived_instance "DerivedInstance1"
derived_instance "DerivedInstance2"
position "Position13"
sketch "btm" plane through (0, 0, -55) normal (0, 0, -1) x axis (1, 0, 0)
  line L1 (17.5, 30.7246) -> (-17.5, 30.7246)
  line L2 (-17.5, -30.7246) -> (17.5, -30.7246)
  curve K1 (-20.8113, 34.4824) -> (-27.9104, 39.7996)
  curve K2 (-48.969, 26.4968) -> (-47.2168, 17.802)
  curve K3 (-47.2168, -17.802) -> (-48.969, -26.4968)
  curve K4 (-27.9104, -39.7996) -> (-20.8113, -34.4824)
  line L3 (15.2717, -34.641) -> (-17.5, -34.641)
  curve K5 (15.2717, -34.641) -> (21.515, -40.142)
  curve K6 (43.6144, -30.7496) -> (44.3437, -21.8956)
  curve K7 (44.3437, 21.8956) -> (43.6144, 30.7496)
  curve K8 (21.515, 40.142) -> (15.2717, 34.641)
  line L4 (-17.5, 34.641) -> (15.2717, 34.641)
  arc A1 centre (-37.8687, 32.2443) radius 10.5 clockwise from (-43.217, 23.2085) to (-27.4117, 33.1928)
  arc A2 centre (-17.5, 0) radius 34.641 clockwise from (-43.217, 23.2085) to (-27.4117, 33.1928)
  arc A3 centre (31.2041, 32.2443) radius 10.5 clockwise from (20.9426, 34.4695) to (39.9277, 26.4007)
  arc A4 centre (17.5, 0) radius 34.641 clockwise from (20.9426, 34.4695) to (39.9277, 26.4007)
  arc A5 centre (31.2041, -32.2443) radius 10.5 clockwise from (39.9277, -26.4007) to (20.9426, -34.4695)
  arc A6 centre (17.5, 0) radius 34.641 clockwise from (39.9277, -26.4007) to (20.9426, -34.4695)
  arc A7 centre (-37.8687, -32.2443) radius 10.5 clockwise from (-27.4117, -33.1928) to (-43.217, -23.2085)
  arc A8 centre (-17.5, 0) radius 34.641 clockwise from (-27.4117, -33.1928) to (-43.217, -23.2085)
  arc A9 centre (-17.5, 0) radius 30.7246 clockwise from (-17.5, -30.7246) to (-17.5, 30.7246)
  arc A10 centre (17.5, 0) radius 30.7246 clockwise from (17.5, 30.7246) to (17.5, -30.7246)
  arc A11 centre (-17.5, 0) radius 34.641 clockwise from (-20.8113, 34.4824) to (-17.5, 34.641)
  arc A12 centre (-37.8687, 32.2443) radius 12.5 clockwise from (-48.969, 26.4968) to (-27.9104, 39.7996)
  arc A13 centre (-17.5, 0) radius 34.641 clockwise from (-47.2168, -17.802) to (-47.2168, 17.802)
  arc A14 centre (-37.8687, -32.2443) radius 12.5 clockwise from (-27.9104, -39.7996) to (-48.969, -26.4968)
  arc A15 centre (-17.5, 0) radius 34.641 clockwise from (-17.5, -34.641) to (-20.8113, -34.4824)
  arc A16 centre (31.2041, -32.2443) radius 12.5 clockwise from (43.6144, -30.7496) to (21.515, -40.142)
  arc A17 centre (17.5, 0) radius 34.641 clockwise from (44.3437, 21.8956) to (44.3437, -21.8956)
  arc A18 centre (31.2041, 32.2443) radius 12.5 clockwise from (21.515, 40.142) to (43.6144, 30.7496)
  arc A19 centre (34.2917, -30.336) radius 6.8739 clockwise from (36.7751, -23.9263) to (39.9277, -26.4007)
  arc A20 centre (31.8067, -32.1137) radius 11.1166 clockwise from (20.9426, -34.4695) to (20.801, -30.5467)
  point P39 (36.7751, -23.9263)
  point P11 (39.9277, -26.4007)
  point P38 (39.9277, -26.4007)
  point P42 (20.801, -30.5467)
  point P10 (20.9426, -34.4695)
  point P41 (20.9426, -34.4695)
  coincident A10 P39
  coincident P11 P38
  tangent A5 A20
  coincident A10 P42
  coincident P10 P41
extrude "Extrude153" cut sketch "btm" profile of A5 A6 against normal blind 10
extrude "Extrude154" new body sketch "btm" profile of A5 A6 to an object bodies "solwall"
position "Position14"
extrude "Extrude155" cut sketch "Sketch5" blind 28
extrude "Extrude156" cut sketch "Sketch5" blind 19
extrude "Extrude157" cut of existing geometry blind 14
extrude "Extrude158" cut of existing geometry blind -6.5
extrude "Extrude159" cut of existing geometry blind -59
extrude "Extrude160" cut of existing geometry blind -42
extrude "Extrude161" cut of existing geometry blind -1
extrude "Extrude162" cut of existing geometry blind -1
offset_faces "OffsetFaces8" distance -0.2
work_plane "WorkPlane7" AlongDistance -34
split "Split10"
remove_body "RemoveBody30"
extrude "Extrude163" cut of existing geometry blind -0.55
extrude "Extrude164" cut of existing geometry blind -4.5
offset_faces "OffsetFaces9" distance -0.2
offset_faces "OffsetFaces10" distance -0.2
extrude "Extrude165" cut sketch "btm" profile of A6 A10 A19 A20 against normal blind 5
remove_body "RemoveBody31"
extrude "Extrude180" new body sketch "Sketch33" profile of L1 L3 L5 L6 L7 A46 L26 A45 A51 A52 L30 L31 L32 L33 L34 L35 along normal blind 4
external_derived "Sketch1"
derived_instance "DerivedInstance8"
move "Move1"
position "Position16"
sketch "switchsketch" plane through (0, 0, -61.99) normal (0, 0, -1) x axis (1, 0, 0)
  line L1 (16.7, 2.7) -> (16.7, -3.1)
  line L2 (-2.7, 2.7) -> (16.7, 2.7)
  line L3 (-2.7, -3.1) -> (-2.7, 2.7)
  line L4 (16.7, -3.1) -> (-2.7, -3.1)
  line L5 (10.4, -1.8) -> (4.2, -1.8)
  line L6 (10.4, -1.8) -> (10.4, 1.4)
  line L7 (7.3, 1.4) -> (10.4, 1.4)
  line L8 (4.2, 1.4) -> (7.3, 1.4)
  line L9 (4.2, -1.8) -> (4.2, 1.4)
  circle C1 centre (-0.2, -0.2) radius 1.5
  circle C2 centre (14.2, -0.2) radius 1.5
extrude "Extrude182" cut sketch "switchsketch" profile of C1 C2 along normal blind 0 and along normal blind 4
extrude "Extrude183" cut sketch "switchsketch" profile of L9 L8 L7 L6 L5 along normal blind 35
sketch "Sketch44" plane through (0, 53, 0) normal (0, 1, 0) x axis (-1, 0, 0)
  line L1 (-24.0366, 29.5563) -> (-24.0366, 28.5313)
  line L2 (-44.7705, -1) -> (-44.7705, 1)
  line L3 (17.5, -30.2705) -> (-17.5, -30.2705)
  line L4 (44.7705, 1) -> (44.7705, -1)
  line L5 (21.6272, 28.9781) -> (21.6272, 29.9878)
  line L6 (-20.316, 26) -> (17.76, 26)
  line L7 (0, -19.2705) -> (0, -30.2705)
  line L8 (-9.5, -19.2705) -> (9.5, -19.2705)
  line L9 (-9.5, -30.2705) -> (-9.5, -19.2705)
  line L10 (9.5, -30.2705) -> (-9.5, -30.2705)
  line L11 (9.5, -19.2705) -> (9.5, -30.2705)
  line L12 (-9.5, -30.2705) -> (9.5, -19.2705)
  line L13 (9.5, -30.2705) -> (-9.5, -19.2705)
  arc A1 centre (-17.5, 0) radius 30.2705 clockwise from (-47.3435, 5.0665) to (-24.0366, 29.5563)
  arc A2 centre (-49.2705, 1) radius 4.5 clockwise from (-47.3435, 5.0665) to (-44.7705, 1)
  arc A3 centre (-49.2705, -1) radius 4.5 clockwise from (-44.7705, -1) to (-47.3435, -5.0665)
  arc A4 centre (-17.5, 0) radius 30.2705 clockwise from (-17.5, -30.2705) to (-47.3435, -5.0665)
  arc A5 centre (17.5, 0) radius 30.2705 clockwise from (47.3435, -5.0665) to (17.5, -30.2705)
  arc A6 centre (49.2705, -1) radius 4.5 clockwise from (47.3435, -5.0665) to (44.7705, -1)
  arc A7 centre (49.2705, 1) radius 4.5 clockwise from (44.7705, 1) to (47.3435, 5.0665)
  arc A8 centre (17.5, 0) radius 30.2705 clockwise from (21.6272, 29.9878) to (47.3435, 5.0665)
  arc A9 centre (17.76, 30) radius 4 clockwise from (21.6272, 28.9781) to (17.76, 26)
  arc A10 centre (-20.316, 30) radius 4 clockwise from (-20.316, 26) to (-24.0366, 28.5313)
  arc A11 centre (0, -28.8728) radius 9.6023 clockwise from (-9.5, -30.2705) to (9.5, -30.2705)
  point P26 (0, -30.2705)
  point P32 (0, -24.7705)
  point P27 (0, -19.2705)
  point P30 (-9.5, -30.2705)
  point P31 (9.5, -30.2705)
  point P29 (-9.5, -19.2705)
  midpoint L3 P26
  perpendicular L3 L7
  horizontal L8
  perpendicular L8 L9
  parallel L8 L10
  parallel L9 L11
  coincident L12 P32
  coincident L13 P32
  midpoint L7 P32
  coincident P27 A11
  dimension "d743" distance P26 P27 = 11
  dimension "d744" distance P30 P31 = 19
  dimension "d745" distance P29 P30 = 11
extrude "Extrude184" cut sketch "Sketch44" profile of L3 A11 against normal blind 45
offset_faces "OffsetFaces11" distance -0.1
offset_faces "OffsetFaces12" distance -0.1
offset_faces "OffsetFaces13" distance -1
offset_faces "OffsetFaces14" distance 0.45
sketch "neosonplate" plane through (0, 0, 34.7705) normal (0, 0, 1) x axis (1, 0, 0)
  line L1 (-17.486, 0) -> (20, 0)
  circle C1 centre (0, -32) radius 5
  circle C2 centre (0, -32) radius 6
  circle C3 centre (0, -32) radius 4
  circle C4 centre (0, -32) radius 7
  circle C5 centre (0, 32) radius 4
  circle C6 centre (0, 32) radius 5
  circle C7 centre (0, 32) radius 6
  circle C8 centre (0, 32) radius 7
  symmetric C1 L1 C6
  symmetric C2 L1 C7
  symmetric C3 L1 C5
  symmetric C4 L1 C8
  dimension "d752" diameter C1 = 10
  dimension "d753" = 1
  dimension "d763" = -1
  dimension "d768" = 1
extrude "Extrude185" cut sketch "neosonplate" profile of C1 against normal blind 11
extrude "Extrude186" add sketch "neosonplate" profile of C1 C2 C5 C6 against normal blind 6
extrude "Extrude187" add sketch "neosonplate" profile of C1 C3 C6 C7 against normal blind 6
extrude "Extrude188" cut sketch "neosonplate" profile of C1 C3 C5 against normal blind 5
extrude "Extrude189" cut sketch "neosonplate" profile of C3 C5 against normal blind 14
extrude "Extrude192" cut sketch "neosonplate" profile of C5 C6 against normal blind 5
extrude "Extrude193" add sketch "neosonplate" profile of C2 C4 C7 C8 against normal blind 6
extrude "Extrude194" new body sketch "neosonplate" profile of C1 C3 C5 C6 against normal blind 5 bodies "neoacr1", "neoacr2"
extrude "Extrude195" cut of existing geometry blind -3.2
remove_body "RemoveBody32"
remove_body "RemoveBody33"
combine "Combine13" bodies "drawerfront", "drawer"
sketch "Sketch46" plane through (0, 0, -41.51) normal (0, 0, -1) x axis (1, 0, 0)
  line L1 (-34.152, 4.775) -> (34.619, 4.775)
  line L2 (-36.152, -31.833) -> (-36.152, 2.775)
  line L3 (34.619, -33.833) -> (-34.152, -33.833)
  line L4 (36.619, 2.775) -> (36.619, -31.833)
  line L5 (20.7838, -33.5357) -> (26.1808, -33.5357)
  line L6 (26.1808, -30.4187) -> (26.1808, -33.5357)
  line L7 (26.1808, -30.4187) -> (34.0742, -30.4187)
  line L8 (36.619, -28.6719) -> (34.0742, -30.4187)
  line L9 (36.619, -28.6719) -> (36.619, -23.2483)
  line L10 (20.7838, -33.833) -> (20.7838, -33.5357)
  line L11 (20.7838, -23.2483) -> (36.619, -23.2483)
  line L12 (20.7838, -33.833) -> (20.7838, -23.2483)
  line L13 (36.619, -33.833) -> (36.619, -28.6719)
  line L14 (36.619, -33.833) -> (20.7838, -33.833)
  arc A1 centre (34.619, 2.775) radius 2 clockwise from (34.619, 4.775) to (36.619, 2.775)
  arc A2 centre (-34.152, 2.775) radius 2 clockwise from (-36.152, 2.775) to (-34.152, 4.775)
  arc A3 centre (-34.152, -31.833) radius 2 clockwise from (-34.152, -33.833) to (-36.152, -31.833)
  arc A4 centre (34.619, -31.833) radius 2 clockwise from (36.619, -31.833) to (34.619, -33.833)
  circle C1 centre (-31.199, -29.007) radius 1.6
  circle C2 centre (31.285, -0.686) radius 1.6
  point P20 (36.619, -23.2483)
  point P21 (36.619, -28.6719)
  point P22 (20.7838, -33.833)
  perpendicular L5 L6
  perpendicular L6 L7
  coincident L4 P20
  coincident L4 P21
  coincident L3 P22
  perpendicular L3 L10
  perpendicular L10 L11
  perpendicular L3 L12
  parallel L4 L13
  perpendicular L13 L14
component_insert "Component Insert"
split "Split11" bodies "tail (1)"
work_plane "WorkPlane8" AlongDistance -82
sketch "Sketch48" plane through (-82, 0, 0) normal (1, 0, 0) x axis (0, 1, 0)
  curve K1 (4.4805, -1.4179) -> (4.4805, -1.4179)
  curve K2 (4.4805, -1.4179) -> (4.4805, -1.4179)
  line L1 (5.9266, -0.4765) -> (-6.2372, -0.4765)
  line L2 (0.3216, -6.9565) -> (0.4732, 6.0259)
  curve K3 (6.8772, 1.6302) -> (4.4805, -1.4179)
  curve K4 (6.8772, 1.6302) -> (6.878, 1.6304)
  line L3 (6.878, 1.6304) -> (6.8772, 1.6302)
  curve K5 (6.8772, 1.6302) -> (4.4805, -1.4179)
  circle C1 centre (0.3974, -0.4653) radius 4.5
  point P6 (-6.2372, -0.4765)
  point P8 (0.4732, 6.0259)
  point P9 (0.3216, -6.9565)
  point P10 (0.3974, -0.4653)
  coincident K2 P6
  horizontal L1
  coincident K2 P8
  coincident K1 P9
  midpoint L2 P10
  dimension "d780" diameter C1 = 9
extrude "Extrude196" add sketch "Sketch48" profile of K1 K2 C1 against normal blind 3
extrude "Extrude197" add of existing geometry blind 3
position "Position17"
position "Position18"
extrude "Extrude1" cut of existing geometry blind -1.5
extrude "Extrude2" add of existing geometry to an object
mirror "Mirror1" mirrorStitchTolerance 0.1 bodies "Body1 (1)"
offset_faces "OffsetFaces1" distance 0.5
work_plane "WorkPlane9" AlongDistance -35
split "Split2" bodies "Body1 (2)", "Body1 (1) (1)"
combine "Combine14"
sketch "Sketch50" plane through (0, 0, -66) normal (0, 0, -1) x axis (1, 0, 0)
  curve K1 (34.0494, -20.0725) -> (20.4661, -25.8455)
  line L1 (36.3634, -39.466) -> (37.5634, -39.466)
  line L2 (27.3808, -39.466) -> (36.3634, -39.466)
  line L3 (26.1808, -39.466) -> (27.3808, -39.466)
  line L4 (26.1808, -33.5357) -> (26.1808, -39.466)
  line L5 (36.3634, -30.4187) -> (34.0742, -30.4187)
  line L6 (37.5634, -30.4187) -> (36.3634, -30.4187)
  line L7 (37.5634, -39.466) -> (37.5634, -30.4187)
  curve K2 (-27.4117, -33.1928) -> (-43.217, -23.2085)
  curve K3 (-43.217, 23.2085) -> (-27.4117, 33.1928)
  curve K4 (20.9426, 34.4695) -> (39.9277, 26.4007)
  line L8 (-43.9368, -40.8134) -> (-36.0006, -29.287)
  line L9 (2.5, 0) -> (20, 0)
  line L10 (35.532, 41.8109) -> (31.0497, 31.8811)
  arc A1 centre (31.2041, -32.2443) radius 12.5 clockwise from (34.0494, -20.0725) to (20.4661, -25.8455)
  arc A2 centre (17.5, 0) radius 34.641 clockwise from (26.1808, -33.5357) to (20.9426, -34.4695)
  arc A3 centre (31.2041, -32.2443) radius 10.5 clockwise from (39.9277, -26.4007) to (20.9426, -34.4695)
  arc A4 centre (17.5, 0) radius 34.641 clockwise from (39.9277, -26.4007) to (34.0742, -30.4187)
  arc A5 centre (-17.5, 0) radius 34.641 clockwise from (-27.4117, -33.1928) to (-43.217, -23.2085)
  arc A6 centre (-17.5, 0) radius 34.641 clockwise from (-43.217, 23.2085) to (-27.4117, 33.1928)
  arc A7 centre (17.5, 0) radius 34.641 clockwise from (20.9426, 34.4695) to (39.9277, 26.4007)
  circle C1 centre (-39.9687, -35.0502) radius 1.05
  circle C2 centre (-39.9687, -35.0502) radius 3.5
  circle C3 centre (-39.9687, 35.0502) radius 3.5
  circle C4 centre (-39.9687, 35.0502) radius 1.05
  circle C5 centre (33.2908, 36.846) radius 1.05
  circle C6 centre (33.2908, 36.846) radius 3.5
  circle C7 centre (33.2908, -36.846) radius 1.05
  circle C8 centre (33.2908, -36.846) radius 3.5
  circle C9 centre (-39.9687, 35.0502) radius 5.5
  circle C10 centre (-39.9687, -35.0502) radius 5.5
  circle C11 centre (33.2908, 36.846) radius 5.5
  point P26 (-36.0006, -29.287)
  point P27 (-43.9368, -40.8134)
  point P28 (-39.9687, -35.0502)
  point P34 (31.0497, 31.8811)
  point P35 (35.532, 41.8109)
  point P36 (33.2908, 36.846)
  midpoint A5 P26
  coincident K2 P27
  midpoint L8 P28
  concentric C1 C2
  symmetric C1 L9 C4
  symmetric C2 L9 C3
  midpoint A7 P34
  coincident K4 P35
  midpoint L10 P36
  concentric C5 C6
  symmetric L9 C5 C7
  symmetric L9 C6 C8
  dimension "d793" diameter C1 = 2.1
  dimension "d794" diameter C2 = 7
  dimension "d795" diameter C5 = 2.1
  dimension "d796" diameter C6 = 7
  dimension "d801" = 2
  dimension "d802" = 2
  dimension "d803" = 2
extrude "Extrude201" add sketch "Sketch50" profile of C1 C2 against normal blind 6
extrude "Extrude202" add sketch "Sketch50" profile of A7 K4 C1 C2 C3 C4 C5 C6 C9 C10 C11 against normal blind 8
extrude "Extrude203" cut sketch "Sketch50" profile of C1 C2 C3 C4 C5 C6 against normal blind 6
extrude "Extrude204" cut sketch "Sketch50" profile of C1 C4 C5 against normal blind 10
extrude "Extrude205" add sketch "Sketch50" profile of C3 C4 to an object
extrude "Extrude206" add sketch "Sketch50" profile of C1 C2 to an object
extrude "Extrude207" add sketch "Sketch50" profile of C5 C6 to an object
extrude "Extrude209" cut sketch "Sketch50" profile of C1 C2 C3 C4 C5 C6 against normal blind 8
extrude "Extrude210" cut of existing geometry to an object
